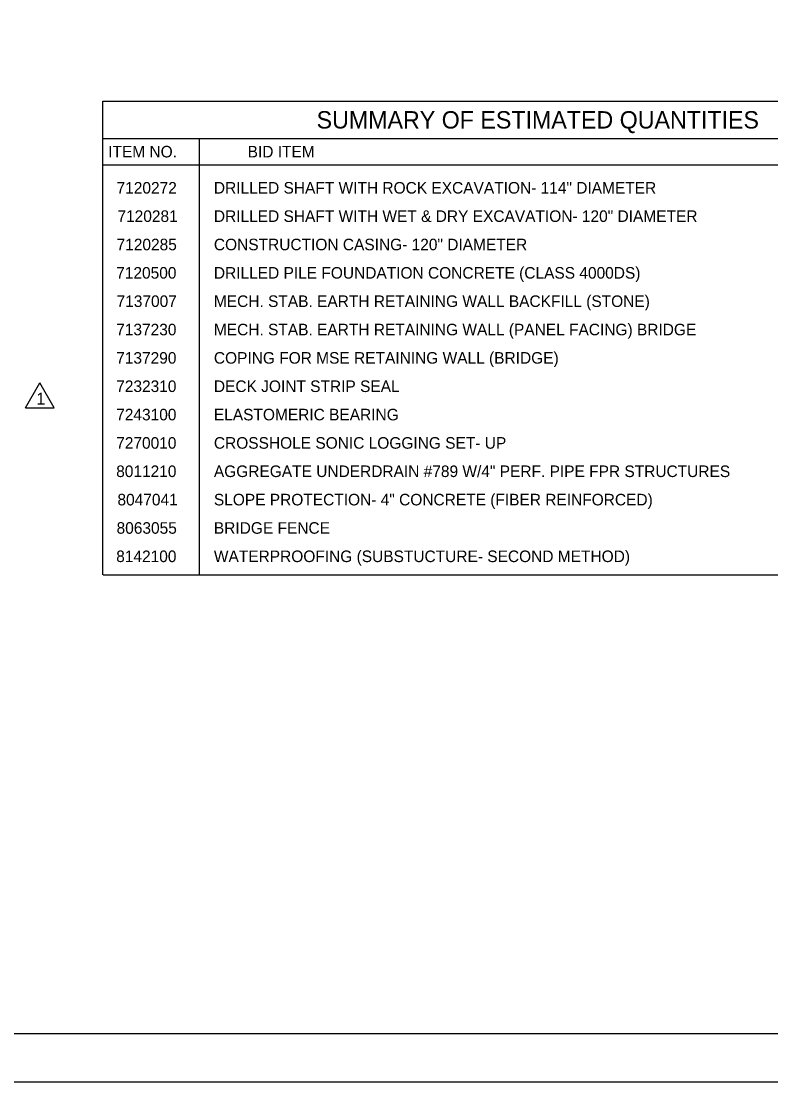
# Model space of a CAD drawing. Extents: x -125.5 to -89.4, y -5.1 to 16.9.
# Drawn here: x -111.65 to -103.88, y -5.07 to 5.93 of the extents above; entities that cross this region are included whole.
import ezdxf

# ---------------------------------------------------------------- set-up
doc = ezdxf.new("R2010")
doc.units = 0
for name, color, linetype in [('BR_BORDER LINES', 7, 'Continuous'), ('BR_TABLE LINES', 7, 'Continuous'), ('BR_TEXT', 7, 'Continuous'), ('Level 31', 7, 'Continuous')]:
    doc.layers.add(name, color=color, linetype=linetype)

msp = doc.modelspace()

# ---------------------------------------------------------------- linework, layer by layer
at = {"layer": 'BR_BORDER LINES'}
msp.add_line((-123.699, -4.566), (-90.033, -4.566), dxfattribs=at)
at = {"layer": 'BR_TABLE LINES'}
for p, q in [((-110.806, 5.106), (-100.906, 5.106)), ((-110.806, 0.193), (-110.806, 5.106)), ((-110.806, 4.716), (-100.906, 4.716)), ((-109.806, 0.193), (-109.806, 4.716)), ((-110.806, 4.446), (-100.906, 4.446)), ((-110.803, 0.193), (-100.906, 0.193))]:
    msp.add_line(p, q, dxfattribs=at)
at = {"layer": 'BR_TEXT'}
for p, q in [((-111.611, 1.923), (-111.461, 2.183)), ((-111.311, 1.923), (-111.461, 2.183)), ((-111.611, 1.923), (-111.311, 1.923))]:
    msp.add_line(p, q, dxfattribs=at)
at = {"layer": 'Level 31'}
msp.add_lwpolyline([(-125.533, -5.066), (-89.533, -5.066), (-89.533, 16.934), (-125.533, 16.934)], close=True, dxfattribs=at)

# ---------------------------------------------------------------- texts
at = {"layer": 'BR_TEXT'}
for s, height, p in [('SUMMARY OF ESTIMATED QUANTITIES', 0.18, (-108.591, 4.821)), ('ITEM NO.', 0.12, (-110.752, 4.521)), ('BID ITEM', 0.12, (-109.306, 4.521)), ('7120272', 0.12, (-110.665, 4.146)), ('DRILLED SHAFT WITH ROCK EXCAVATION- 114" DIAMETER', 0.12, (-109.656, 4.146)), ('7120281', 0.12, (-110.656, 3.852)), ('DRILLED SHAFT WITH WET & DRY EXCAVATION- 120" DIAMETER', 0.12, (-109.656, 3.852)), ('7120285', 0.12, (-110.665, 3.558)), ('CONSTRUCTION CASING- 120" DIAMETER', 0.12, (-109.656, 3.558)), ('7120500', 0.12, (-110.669, 3.264)), ('DRILLED PILE FOUNDATION CONCRETE (CLASS 4000DS)', 0.12, (-109.656, 3.264)), ('7137007', 0.12, (-110.665, 2.97)), ('MECH. STAB. EARTH RETAINING WALL BACKFILL (STONE)', 0.12, (-109.656, 2.97)), ('7137230', 0.12, (-110.669, 2.676)), ('MECH. STAB. EARTH RETAINING WALL (PANEL FACING) BRIDGE', 0.12, (-109.656, 2.676)), ('7137290', 0.12, (-110.669, 2.382)), ('COPING FOR MSE RETAINING WALL (BRIDGE)', 0.12, (-109.656, 2.382)), ('7232310', 0.12, (-110.669, 2.088)), ('DECK JOINT STRIP SEAL', 0.12, (-109.656, 2.088)), ('7243100', 0.12, (-110.669, 1.794)), ('ELASTOMERIC BEARING', 0.12, (-109.656, 1.794)), ('7270010', 0.12, (-110.669, 1.5)), ('CROSSHOLE SONIC LOGGING SET- UP', 0.12, (-109.656, 1.5)), ('8011210', 0.12, (-110.669, 1.206)), ('AGGREGATE UNDERDRAIN #789 W/4" PERF. PIPE FPR STRUCTURES', 0.12, (-109.656, 1.206)), ('8047041', 0.12, (-110.656, 0.912)), ('SLOPE PROTECTION- 4" CONCRETE (FIBER REINFORCED)', 0.12, (-109.656, 0.912)), ('8063055', 0.12, (-110.665, 0.618)), ('BRIDGE FENCE', 0.12, (-109.656, 0.618)), ('8142100', 0.12, (-110.669, 0.324)), ('WATERPROOFING (SUBSTUCTURE- SECOND METHOD)', 0.12, (-109.656, 0.324))]:
    msp.add_text(s, height=height, dxfattribs=at).set_placement(p)
msp.add_text('1', height=0.125, rotation=360, dxfattribs=at).set_placement((-111.497, 1.957))

doc.saveas('drawing.dxf')
